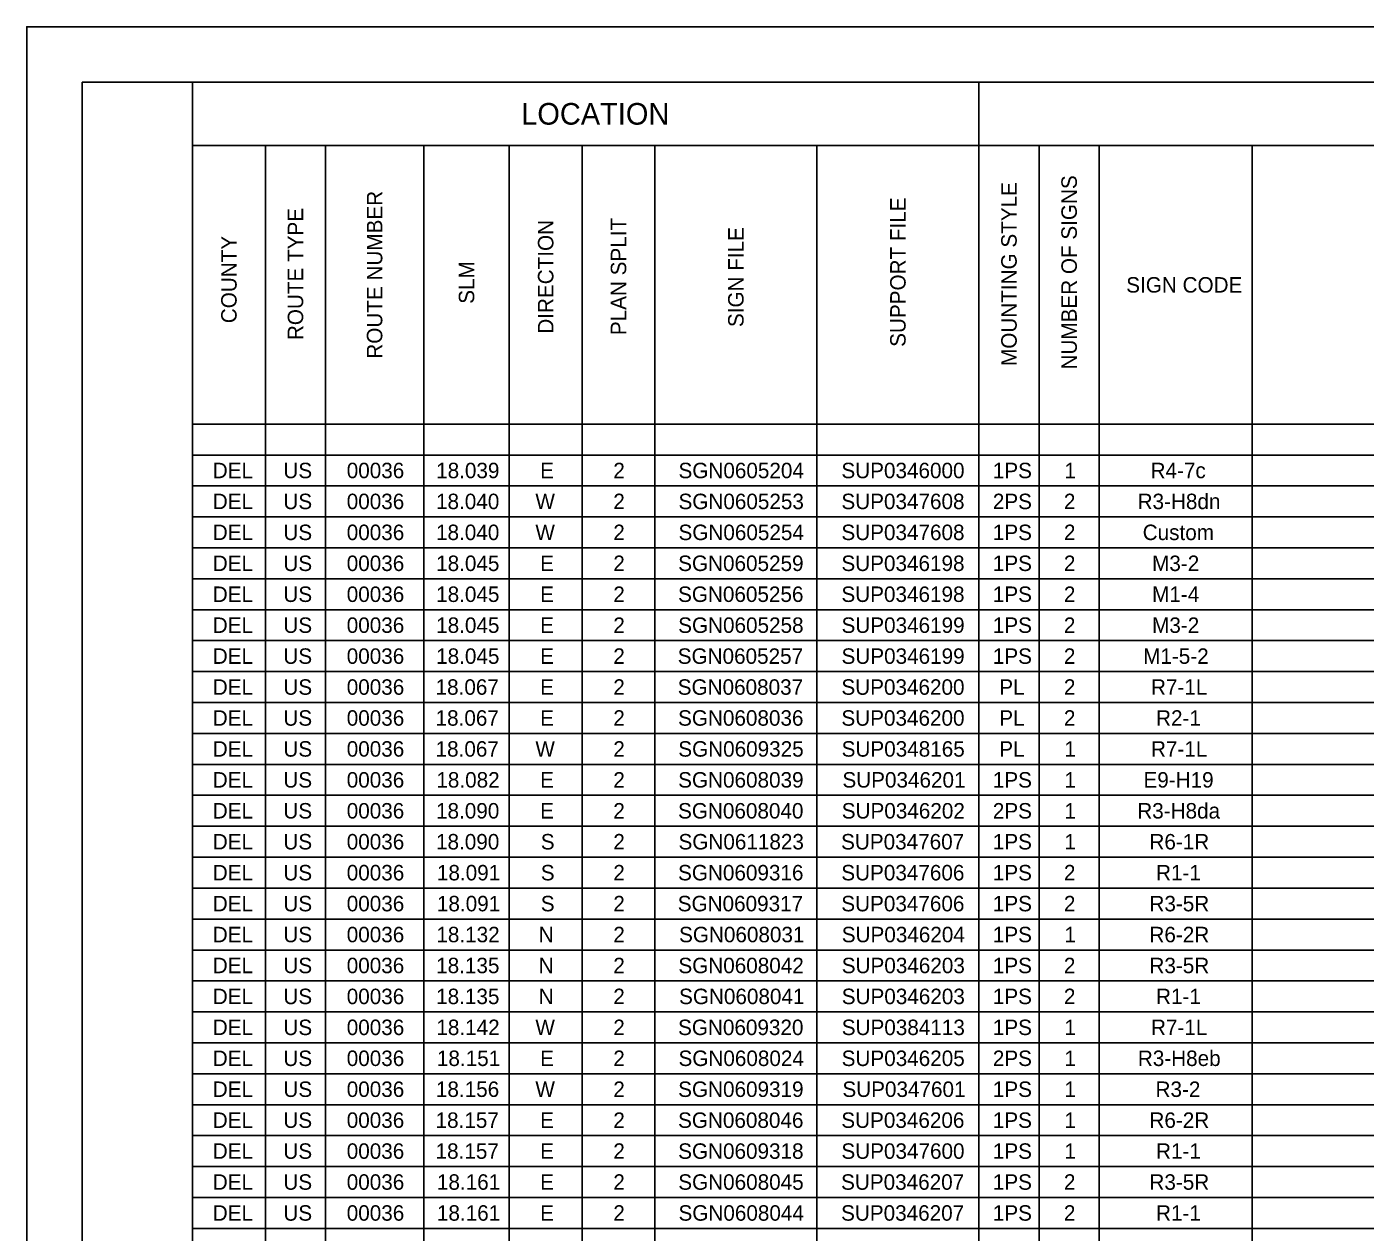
# Model space of a CAD drawing. Extents: x 0 to 34, y 0 to 22.
# Drawn here: x 0 to 12.11, y 11.09 to 22 of the extents above; entities that cross this region are included whole.
import ezdxf

# ---------------------------------------------------------------- set-up
doc = ezdxf.new("R2010")
doc.units = 0
for name, color, linetype in [('SH_Border', 7, 'Continuous'), ('SH_Cut_Line', 7, 'Continuous'), ('SH_Data', 7, 'Continuous'), ('SH_Text', 7, 'Continuous')]:
    doc.layers.add(name, color=color, linetype=linetype)

msp = doc.modelspace()

# ---------------------------------------------------------------- linework, layer by layer
at = {"layer": 'SH_Border'}
for points in [[(0.5, 21.5), (1.5, 21.5), (1.5, 0.5), (0.5, 0.5)], [(1.5, 21.5), (33.5, 21.5), (33.5, 0.5), (1.5, 0.5)]]:
    msp.add_lwpolyline(points, close=True, dxfattribs=at)
at = {"layer": 'SH_Cut_Line'}
msp.add_lwpolyline([(0, 0), (34, 0), (34, 22), (0, 22)], close=True, dxfattribs=at)
at = {"layer": 'SH_Data'}
for p, q in [((1.5, 21.5), (32.004, 21.5)), ((8.615, 21.5), (8.615, 0.764)), ((1.5, 20.924), (28.232, 20.924)), ((1.5, 20.924), (1.5, 0.764)), ((2.159, 20.924), (2.159, 0.764)), ((2.702, 20.924), (2.702, 0.764)), ((3.592, 20.924), (3.592, 0.764)), ((4.366, 20.924), (4.366, 0.764)), ((5.025, 20.924), (5.025, 0.764)), ((5.684, 20.924), (5.684, 0.764)), ((7.149, 20.924), (7.149, 0.764)), ((9.159, 20.924), (9.159, 0.764)), ((9.702, 20.924), (9.702, 0.764)), ((11.086, 20.924), (11.086, 0.764)), ((1.5, 18.404), (32.004, 18.404)), ((1.5, 18.124), (32.004, 18.124)), ((1.5, 17.844), (32.004, 17.844)), ((1.5, 17.564), (32.004, 17.564)), ((1.5, 17.284), (32.004, 17.284)), ((1.5, 17.004), (32.004, 17.004)), ((1.5, 16.724), (32.004, 16.724)), ((1.5, 16.444), (32.004, 16.444)), ((1.5, 16.164), (32.004, 16.164)), ((1.5, 15.884), (32.004, 15.884)), ((1.5, 15.604), (32.004, 15.604)), ((1.5, 15.324), (32.004, 15.324)), ((1.5, 15.044), (32.004, 15.044)), ((1.5, 14.764), (32.004, 14.764)), ((1.5, 14.484), (32.004, 14.484)), ((1.5, 14.204), (32.004, 14.204)), ((1.5, 13.924), (32.004, 13.924)), ((1.5, 13.644), (32.004, 13.644)), ((1.5, 13.364), (32.004, 13.364)), ((1.5, 13.084), (32.004, 13.084)), ((1.5, 12.804), (32.004, 12.804)), ((1.5, 12.524), (32.004, 12.524)), ((1.5, 12.244), (32.004, 12.244)), ((1.5, 11.964), (32.004, 11.964)), ((1.5, 11.684), (32.004, 11.684)), ((1.5, 11.404), (32.004, 11.404)), ((1.5, 11.124), (32.004, 11.124))]:
    msp.add_line(p, q, dxfattribs=at)

# ---------------------------------------------------------------- texts
at = {"layer": 'SH_Text'}
for s, height, p in [('LOCATION', 0.196, (4.474, 21.114)), ('SIGN CODE', 0.14, (9.948, 19.594)), ('DEL', 0.14, (1.683, 17.914)), ('US', 0.14, (2.322, 17.914)), ('00036', 0.14, (2.895, 17.914)), ('18.039', 0.14, (3.704, 17.914)), ('E', 0.14, (4.645, 17.914)), ('2', 0.14, (5.307, 17.914)), ('SGN0605204', 0.14, (5.897, 17.914)), ('SUP0346000', 0.14, (7.371, 17.914)), ('1PS', 0.14, (8.741, 17.914)), ('1', 0.14, (9.389, 17.914)), ('R4-7c', 0.14, (10.168, 17.914)), ('DEL', 0.14, (1.683, 17.634)), ('US', 0.14, (2.322, 17.634)), ('00036', 0.14, (2.895, 17.634)), ('18.040', 0.14, (3.703, 17.634)), ('W', 0.14, (4.602, 17.634)), ('2', 0.14, (5.307, 17.634)), ('SGN0605253', 0.14, (5.897, 17.634)), ('SUP0347608', 0.14, (7.371, 17.634)), ('2PS', 0.14, (8.741, 17.634)), ('2', 0.14, (9.384, 17.634)), ('R3-H8dn', 0.14, (10.051, 17.634)), ('DEL', 0.14, (1.683, 17.354)), ('US', 0.14, (2.322, 17.354)), ('00036', 0.14, (2.895, 17.354)), ('18.040', 0.14, (3.703, 17.354)), ('W', 0.14, (4.602, 17.354)), ('2', 0.14, (5.307, 17.354)), ('SGN0605254', 0.14, (5.897, 17.354)), ('SUP0347608', 0.14, (7.371, 17.354)), ('1PS', 0.14, (8.741, 17.354)), ('2', 0.14, (9.384, 17.354)), ('Custom', 0.14, (10.097, 17.354)), ('DEL', 0.14, (1.683, 17.074)), ('US', 0.14, (2.322, 17.074)), ('00036', 0.14, (2.895, 17.074)), ('18.045', 0.14, (3.704, 17.074)), ('E', 0.14, (4.645, 17.074)), ('2', 0.14, (5.307, 17.074)), ('SGN0605259', 0.14, (5.894, 17.074)), ('SUP0346198', 0.14, (7.371, 17.074)), ('1PS', 0.14, (8.741, 17.074)), ('2', 0.14, (9.384, 17.074)), ('M3-2', 0.14, (10.182, 17.074)), ('DEL', 0.14, (1.683, 16.794)), ('US', 0.14, (2.322, 16.794)), ('00036', 0.14, (2.895, 16.794)), ('18.045', 0.14, (3.704, 16.794)), ('E', 0.14, (4.645, 16.794)), ('2', 0.14, (5.307, 16.794)), ('SGN0605256', 0.14, (5.893, 16.794)), ('SUP0346198', 0.14, (7.371, 16.794)), ('1PS', 0.14, (8.741, 16.794)), ('2', 0.14, (9.384, 16.794)), ('M1-4', 0.14, (10.182, 16.794)), ('DEL', 0.14, (1.683, 16.514)), ('US', 0.14, (2.322, 16.514)), ('00036', 0.14, (2.895, 16.514)), ('18.045', 0.14, (3.704, 16.514)), ('E', 0.14, (4.645, 16.514)), ('2', 0.14, (5.307, 16.514)), ('SGN0605258', 0.14, (5.894, 16.514)), ('SUP0346199', 0.14, (7.372, 16.514)), ('1PS', 0.14, (8.741, 16.514)), ('2', 0.14, (9.384, 16.514)), ('M3-2', 0.14, (10.182, 16.514)), ('DEL', 0.14, (1.683, 16.234)), ('US', 0.14, (2.322, 16.234)), ('00036', 0.14, (2.895, 16.234)), ('18.045', 0.14, (3.704, 16.234)), ('E', 0.14, (4.645, 16.234)), ('2', 0.14, (5.307, 16.234)), ('SGN0605257', 0.14, (5.89, 16.234)), ('SUP0346199', 0.14, (7.372, 16.234)), ('1PS', 0.14, (8.741, 16.234)), ('2', 0.14, (9.384, 16.234)), ('M1-5-2', 0.14, (10.101, 16.234)), ('DEL', 0.14, (1.683, 15.954)), ('US', 0.14, (2.322, 15.954)), ('00036', 0.14, (2.895, 15.954)), ('18.067', 0.14, (3.699, 15.954)), ('E', 0.14, (4.645, 15.954)), ('2', 0.14, (5.307, 15.954)), ('SGN0608037', 0.14, (5.89, 15.954)), ('SUP0346200', 0.14, (7.371, 15.954)), ('PL', 0.14, (8.799, 15.954)), ('2', 0.14, (9.384, 15.954)), ('R7-1L', 0.14, (10.172, 15.954)), ('DEL', 0.14, (1.683, 15.674)), ('US', 0.14, (2.322, 15.674)), ('00036', 0.14, (2.895, 15.674)), ('18.067', 0.14, (3.699, 15.674)), ('E', 0.14, (4.645, 15.674)), ('2', 0.14, (5.307, 15.674)), ('SGN0608036', 0.14, (5.893, 15.674)), ('SUP0346200', 0.14, (7.371, 15.674)), ('PL', 0.14, (8.799, 15.674)), ('2', 0.14, (9.384, 15.674)), ('R2-1', 0.14, (10.218, 15.674)), ('DEL', 0.14, (1.683, 15.394)), ('US', 0.14, (2.322, 15.394)), ('00036', 0.14, (2.895, 15.394)), ('18.067', 0.14, (3.699, 15.394)), ('W', 0.14, (4.602, 15.394)), ('2', 0.14, (5.307, 15.394)), ('SGN0609325', 0.14, (5.895, 15.394)), ('SUP0348165', 0.14, (7.373, 15.394)), ('PL', 0.14, (8.799, 15.394)), ('1', 0.14, (9.389, 15.394)), ('R7-1L', 0.14, (10.172, 15.394)), ('DEL', 0.14, (1.683, 15.114)), ('US', 0.14, (2.322, 15.114)), ('00036', 0.14, (2.895, 15.114)), ('18.082', 0.14, (3.706, 15.114)), ('E', 0.14, (4.645, 15.114)), ('2', 0.14, (5.307, 15.114)), ('SGN0608039', 0.14, (5.894, 15.114)), ('SUP0346201', 0.14, (7.38, 15.114)), ('1PS', 0.14, (8.741, 15.114)), ('1', 0.14, (9.389, 15.114)), ('E9-H19', 0.14, (10.104, 15.114)), ('DEL', 0.14, (1.683, 14.834)), ('US', 0.14, (2.322, 14.834)), ('00036', 0.14, (2.895, 14.834)), ('18.090', 0.14, (3.703, 14.834)), ('E', 0.14, (4.645, 14.834)), ('2', 0.14, (5.307, 14.834)), ('SGN0608040', 0.14, (5.893, 14.834)), ('SUP0346202', 0.14, (7.374, 14.834)), ('2PS', 0.14, (8.741, 14.834)), ('1', 0.14, (9.389, 14.834)), ('R3-H8da', 0.14, (10.048, 14.834)), ('DEL', 0.14, (1.683, 14.554)), ('US', 0.14, (2.322, 14.554)), ('00036', 0.14, (2.895, 14.554)), ('18.090', 0.14, (3.703, 14.554)), ('S', 0.14, (4.651, 14.554)), ('2', 0.14, (5.307, 14.554)), ('SGN0611823', 0.14, (5.897, 14.554)), ('SUP0347607', 0.14, (7.368, 14.554)), ('1PS', 0.14, (8.741, 14.554)), ('1', 0.14, (9.389, 14.554)), ('R6-1R', 0.14, (10.158, 14.554)), ('DEL', 0.14, (1.683, 14.274)), ('US', 0.14, (2.322, 14.274)), ('00036', 0.14, (2.895, 14.274)), ('18.091', 0.14, (3.711, 14.274)), ('S', 0.14, (4.651, 14.274)), ('2', 0.14, (5.307, 14.274)), ('SGN0609316', 0.14, (5.893, 14.274)), ('SUP0347606', 0.14, (7.37, 14.274)), ('1PS', 0.14, (8.741, 14.274)), ('2', 0.14, (9.384, 14.274)), ('R1-1', 0.14, (10.218, 14.274)), ('DEL', 0.14, (1.683, 13.994)), ('US', 0.14, (2.322, 13.994)), ('00036', 0.14, (2.895, 13.994)), ('18.091', 0.14, (3.711, 13.994)), ('S', 0.14, (4.651, 13.994)), ('2', 0.14, (5.307, 13.994)), ('SGN0609317', 0.14, (5.89, 13.994)), ('SUP0347606', 0.14, (7.37, 13.994)), ('1PS', 0.14, (8.741, 13.994)), ('2', 0.14, (9.384, 13.994)), ('R3-5R', 0.14, (10.158, 13.994)), ('DEL', 0.14, (1.683, 13.714)), ('US', 0.14, (2.322, 13.714)), ('00036', 0.14, (2.895, 13.714)), ('18.132', 0.14, (3.706, 13.714)), ('N', 0.14, (4.632, 13.714)), ('2', 0.14, (5.307, 13.714)), ('SGN0608031', 0.14, (5.902, 13.714)), ('SUP0346204', 0.14, (7.374, 13.714)), ('1PS', 0.14, (8.741, 13.714)), ('1', 0.14, (9.389, 13.714)), ('R6-2R', 0.14, (10.158, 13.714)), ('DEL', 0.14, (1.683, 13.434)), ('US', 0.14, (2.322, 13.434)), ('00036', 0.14, (2.895, 13.434)), ('18.135', 0.14, (3.704, 13.434)), ('N', 0.14, (4.632, 13.434)), ('2', 0.14, (5.307, 13.434)), ('SGN0608042', 0.14, (5.896, 13.434)), ('SUP0346203', 0.14, (7.374, 13.434)), ('1PS', 0.14, (8.741, 13.434)), ('2', 0.14, (9.384, 13.434)), ('R3-5R', 0.14, (10.158, 13.434)), ('DEL', 0.14, (1.683, 13.154)), ('US', 0.14, (2.322, 13.154)), ('00036', 0.14, (2.895, 13.154)), ('18.135', 0.14, (3.704, 13.154)), ('N', 0.14, (4.632, 13.154)), ('2', 0.14, (5.307, 13.154)), ('SGN0608041', 0.14, (5.902, 13.154)), ('SUP0346203', 0.14, (7.374, 13.154)), ('1PS', 0.14, (8.741, 13.154)), ('2', 0.14, (9.384, 13.154)), ('R1-1', 0.14, (10.218, 13.154)), ('DEL', 0.14, (1.683, 12.874)), ('US', 0.14, (2.322, 12.874)), ('00036', 0.14, (2.895, 12.874)), ('18.142', 0.14, (3.706, 12.874)), ('W', 0.14, (4.602, 12.874)), ('2', 0.14, (5.307, 12.874)), ('SGN0609320', 0.14, (5.893, 12.874)), ('SUP0384113', 0.14, (7.374, 12.874)), ('1PS', 0.14, (8.741, 12.874)), ('1', 0.14, (9.389, 12.874)), ('R7-1L', 0.14, (10.172, 12.874)), ('DEL', 0.14, (1.683, 12.594)), ('US', 0.14, (2.322, 12.594)), ('00036', 0.14, (2.895, 12.594)), ('18.151', 0.14, (3.711, 12.594)), ('E', 0.14, (4.645, 12.594)), ('2', 0.14, (5.307, 12.594)), ('SGN0608024', 0.14, (5.897, 12.594)), ('SUP0346205', 0.14, (7.373, 12.594)), ('2PS', 0.14, (8.741, 12.594)), ('1', 0.14, (9.389, 12.594)), ('R3-H8eb', 0.14, (10.053, 12.594)), ('DEL', 0.14, (1.683, 12.314)), ('US', 0.14, (2.322, 12.314)), ('00036', 0.14, (2.895, 12.314)), ('18.156', 0.14, (3.702, 12.314)), ('W', 0.14, (4.602, 12.314)), ('2', 0.14, (5.307, 12.314)), ('SGN0609319', 0.14, (5.894, 12.314)), ('SUP0347601', 0.14, (7.38, 12.314)), ('1PS', 0.14, (8.741, 12.314)), ('1', 0.14, (9.389, 12.314)), ('R3-2', 0.14, (10.213, 12.314)), ('DEL', 0.14, (1.683, 12.034)), ('US', 0.14, (2.322, 12.034)), ('00036', 0.14, (2.895, 12.034)), ('18.157', 0.14, (3.699, 12.034)), ('E', 0.14, (4.645, 12.034)), ('2', 0.14, (5.307, 12.034)), ('SGN0608046', 0.14, (5.893, 12.034)), ('SUP0346206', 0.14, (7.37, 12.034)), ('1PS', 0.14, (8.741, 12.034)), ('1', 0.14, (9.389, 12.034)), ('R6-2R', 0.14, (10.158, 12.034)), ('DEL', 0.14, (1.683, 11.754)), ('US', 0.14, (2.322, 11.754)), ('00036', 0.14, (2.895, 11.754)), ('18.157', 0.14, (3.699, 11.754)), ('E', 0.14, (4.645, 11.754)), ('2', 0.14, (5.307, 11.754)), ('SGN0609318', 0.14, (5.894, 11.754)), ('SUP0347600', 0.14, (7.371, 11.754)), ('1PS', 0.14, (8.741, 11.754)), ('1', 0.14, (9.389, 11.754)), ('R1-1', 0.14, (10.218, 11.754)), ('DEL', 0.14, (1.683, 11.474)), ('US', 0.14, (2.322, 11.474)), ('00036', 0.14, (2.895, 11.474)), ('18.161', 0.14, (3.711, 11.474)), ('E', 0.14, (4.645, 11.474)), ('2', 0.14, (5.307, 11.474)), ('SGN0608045', 0.14, (5.895, 11.474)), ('SUP0346207', 0.14, (7.368, 11.474)), ('1PS', 0.14, (8.741, 11.474)), ('2', 0.14, (9.384, 11.474)), ('R3-5R', 0.14, (10.158, 11.474)), ('DEL', 0.14, (1.683, 11.194)), ('US', 0.14, (2.322, 11.194)), ('00036', 0.14, (2.895, 11.194)), ('18.161', 0.14, (3.711, 11.194)), ('E', 0.14, (4.645, 11.194)), ('2', 0.14, (5.307, 11.194)), ('SGN0608044', 0.14, (5.897, 11.194)), ('SUP0346207', 0.14, (7.368, 11.194)), ('1PS', 0.14, (8.741, 11.194)), ('2', 0.14, (9.384, 11.194)), ('R1-1', 0.14, (10.218, 11.194))]:
    msp.add_text(s, height=height, dxfattribs=at).set_placement(p)
for s, p in [('NUMBER OF SIGNS', (9.501, 18.898)), ('ROUTE NUMBER', (3.217, 18.996)), ('MOUNTING STYLE', (8.957, 18.93)), ('ROUTE TYPE', (2.501, 19.164)), ('SUPPORT FILE', (7.952, 19.103)), ('DIRECTION', (4.765, 19.222)), ('PLAN SPLIT', (5.424, 19.209)), ('SIGN FILE', (6.486, 19.282)), ('COUNTY', (1.899, 19.317)), ('SLM', (4.049, 19.493))]:
    msp.add_text(s, height=0.14, rotation=90, dxfattribs=at).set_placement(p)

doc.saveas('drawing.dxf')
